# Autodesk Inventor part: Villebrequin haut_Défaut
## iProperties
Shininess: 64.0
Length Units: 11269
Angle Units: 11279
Time Units: 11290
Mass Units: 11283
Length Display Precision: 3
Angle Display Precision: 2
Compacted: True
Part Number: Villebrequin haut_Défaut
Document SubType Name: Modeling
Created: 2006-01
Material: Par défaut
Designer: riri
Density: 0.0
Volumn: 0.0
Area: 0.0
PropertySet Name: Model Information
Control State: 0
Master: False
Checked Out: False
Author: riri
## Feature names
1. Base1
